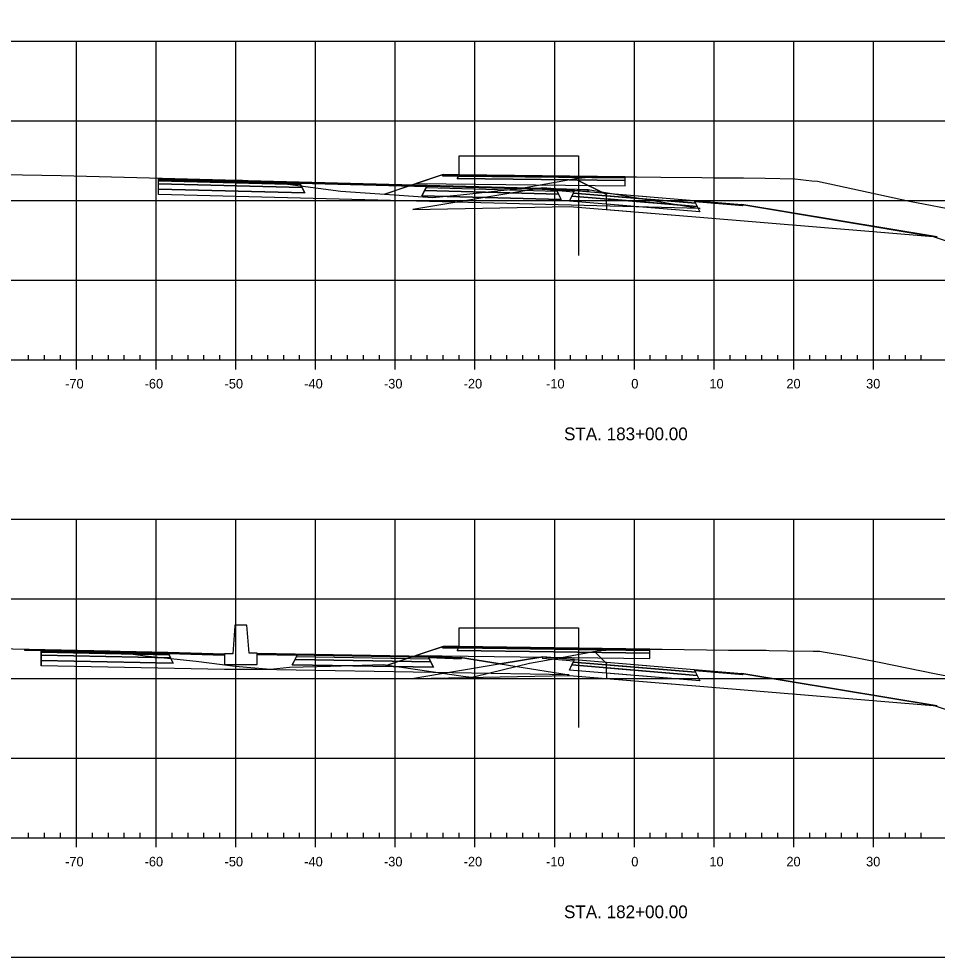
# Model space of a CAD drawing. Extents: x 659657 to 668193, y 633084 to 648639.
# Drawn here: x 667235.3 to 667350.5, y 643502.4 to 643620.2 of the extents above; entities that cross this region are included whole.
import ezdxf

# ---------------------------------------------------------------- set-up
doc = ezdxf.new("R2010")
doc.units = 0
for name, color, linetype in [('Default', 7, 'Continuous'), ('R_Axis', 7, 'Continuous'), ('R_Axis Annot', 7, 'Continuous'), ('R_Exist Surface', 7, 'Continuous'), ('R_Fin Surface', 7, 'Continuous'), ('R_Grid', 7, 'Continuous'), ('R_MOT_Stage 1B', 7, 'Continuous'), ('R_Sub Surface', 7, 'Continuous'), ('T_SIGNAL CONTROL CABINET', 7, 'Continuous'), ('TEMP_SIGNAL_HEAD_STAGE 5', 7, 'Continuous'), ('TEMP_SIGNAL_HEAD_STAGE4', 7, 'Continuous')]:
    doc.layers.add(name, color=color, linetype=linetype)

msp = doc.modelspace()

# ---------------------------------------------------------------- linework, layer by layer
for points in [[(667311.35, 643600.38), (667290.51, 643600.63), (667288.52, 643600.65), (667288.43, 643600.49), (667290.43, 643600.46), (667311.35, 643600.22)], [(667252.8, 643600.2), (667270.44, 643599.74), (667286.54, 643599.33), (667302.64, 643598.91), (667306.66, 643598.75), (667306.75, 643598.58), (667302.72, 643598.74), (667286.46, 643599.16), (667270.53, 643599.57), (667252.8, 643600.03)], [(667320.01, 643597.39), (667320.19, 643597.04), (667304.85, 643598.31), (667305.01, 643598.64)], [(667320.01, 643597.39), (667320.19, 643597.04), (667309.01, 643597.97), (667309.01, 643598.3)], [(667261.1, 643540.48), (667261.1, 643539.14), (667265.18, 643539.14), (667265.18, 643540.56), (667264.16, 643540.56), (667263.89, 643544.06), (667262.39, 643544.06), (667262.39, 643543.98), (667262.12, 643540.48)], [(667314.45, 643541.08), (667290.51, 643541.38), (667288.51, 643541.4), (667288.43, 643541.23), (667290.43, 643541.21), (667314.45, 643540.91)], [(667236.03, 643541.06), (667253.96, 643540.69), (667261.1, 643540.48), (667261.1, 643540.31), (667254.04, 643540.52), (667236.03, 643540.89)], [(667265.18, 643540.56), (667286.61, 643540.18), (667290.69, 643540.03), (667290.78, 643539.86), (667286.69, 643540.01), (667265.18, 643540.4)], [(667320.01, 643538.51), (667320.19, 643538.16), (667304.85, 643539.44), (667305.01, 643539.76)], [(667320.01, 643538.51), (667320.19, 643538.16), (667309.01, 643539.09), (667309.01, 643539.43)]]:
    msp.add_lwpolyline(points, close=True)
at = {"layer": 'Default'}
for points in [[(667281.18, 643598.2), (667282.49, 643598.64), (667285.15, 643599.53), (667288.21, 643600.55), (667288.52, 643600.65), (667289.11, 643600.65), (667290.51, 643600.63), (667306.92, 643600.44), (667311.35, 643600.38)], [(667300.93, 643598.8), (667301.01, 643598.97), (667305.01, 643598.64), (667320.01, 643597.39), (667326.01, 643596.89), (667350.01, 643592.89), (667356.33, 643590.79), (667369.66, 643595.73), (667369.96, 643595.84), (667384.87, 643600.81), (667384.91, 643600.81), (667386.6, 643600.88)], [(667305.04, 643600.12), (667309.01, 643598.14), (667309.01, 643598.3), (667320.01, 643597.39), (667326.01, 643596.89), (667350.01, 643592.89), (667356.33, 643590.79), (667359.49, 643594.1), (667359.56, 643594.18), (667360.58, 643595.23), (667371.01, 643598.68), (667374.76, 643599.21), (667375.02, 643599.25), (667386.6, 643600.88)], [(667281.52, 643539.07), (667282.82, 643539.5), (667285.14, 643540.28), (667286.33, 643540.67), (667288.51, 643541.4), (667289.23, 643541.39), (667290.51, 643541.38), (667299.39, 643541.27), (667314.45, 643541.08)], [(667290.69, 643540.03), (667295.66, 643539.2), (667301.01, 643540.09), (667305.01, 643539.76), (667320.01, 643538.51), (667326.01, 643538.02), (667350.01, 643534.02), (667358.19, 643531.29), (667388.17, 643541.28)], [(667307.49, 643540.78), (667309.01, 643539.26), (667309.01, 643539.43), (667320.01, 643538.51), (667326.01, 643538.02), (667350.01, 643534.02), (667358.19, 643531.29), (667388.17, 643541.28)]]:
    msp.add_lwpolyline(points, dxfattribs=at)
at = {"layer": 'R_Axis'}
for p, q in [((667236.51, 643577.39), (667236.51, 643577.99)), ((667238.51, 643577.39), (667238.51, 643577.99)), ((667240.51, 643577.39), (667240.51, 643577.99)), ((667242.51, 643576.19), (667242.51, 643578.59)), ((667244.51, 643577.39), (667244.51, 643577.99)), ((667246.51, 643577.39), (667246.51, 643577.99)), ((667248.51, 643577.39), (667248.51, 643577.99)), ((667250.51, 643577.39), (667250.51, 643577.99)), ((667252.51, 643576.19), (667252.51, 643578.59)), ((667254.51, 643577.39), (667254.51, 643577.99)), ((667256.51, 643577.39), (667256.51, 643577.99)), ((667258.51, 643577.39), (667258.51, 643577.99)), ((667260.51, 643577.39), (667260.51, 643577.99)), ((667262.51, 643576.19), (667262.51, 643578.59)), ((667264.51, 643577.39), (667264.51, 643577.99)), ((667266.51, 643577.39), (667266.51, 643577.99)), ((667268.51, 643577.39), (667268.51, 643577.99)), ((667270.51, 643577.39), (667270.51, 643577.99)), ((667272.51, 643576.19), (667272.51, 643578.59)), ((667274.51, 643577.39), (667274.51, 643577.99)), ((667276.51, 643577.39), (667276.51, 643577.99)), ((667278.51, 643577.39), (667278.51, 643577.99)), ((667280.51, 643577.39), (667280.51, 643577.99)), ((667282.51, 643576.19), (667282.51, 643578.59)), ((667284.51, 643577.39), (667284.51, 643577.99)), ((667286.51, 643577.39), (667286.51, 643577.99)), ((667288.51, 643577.39), (667288.51, 643577.99)), ((667290.51, 643577.39), (667290.51, 643577.99)), ((667292.51, 643576.19), (667292.51, 643578.59)), ((667294.51, 643577.39), (667294.51, 643577.99)), ((667296.51, 643577.39), (667296.51, 643577.99)), ((667298.51, 643577.39), (667298.51, 643577.99)), ((667300.51, 643577.39), (667300.51, 643577.99)), ((667302.51, 643576.19), (667302.51, 643578.59)), ((667304.51, 643577.39), (667304.51, 643577.99)), ((667306.51, 643577.39), (667306.51, 643577.99)), ((667308.51, 643577.39), (667308.51, 643577.99)), ((667310.51, 643577.39), (667310.51, 643577.99)), ((667312.51, 643576.19), (667312.51, 643578.59)), ((667314.51, 643577.39), (667314.51, 643577.99)), ((667316.51, 643577.39), (667316.51, 643577.99)), ((667318.51, 643577.39), (667318.51, 643577.99)), ((667320.51, 643577.39), (667320.51, 643577.99)), ((667322.51, 643576.19), (667322.51, 643578.59)), ((667324.51, 643577.39), (667324.51, 643577.99)), ((667326.51, 643577.39), (667326.51, 643577.99)), ((667328.51, 643577.39), (667328.51, 643577.99)), ((667330.51, 643577.39), (667330.51, 643577.99)), ((667332.51, 643576.19), (667332.51, 643578.59)), ((667334.51, 643577.39), (667334.51, 643577.99)), ((667336.51, 643577.39), (667336.51, 643577.99)), ((667338.51, 643577.39), (667338.51, 643577.99)), ((667340.51, 643577.39), (667340.51, 643577.99)), ((667342.51, 643576.19), (667342.51, 643578.59)), ((667344.51, 643577.39), (667344.51, 643577.99)), ((667346.51, 643577.39), (667346.51, 643577.99)), ((667348.51, 643577.39), (667348.51, 643577.99)), ((667162.51, 643577.39), (667462.51, 643577.39)), ((667236.51, 643517.39), (667236.51, 643517.99)), ((667238.51, 643517.39), (667238.51, 643517.99)), ((667240.51, 643517.39), (667240.51, 643517.99)), ((667242.51, 643516.19), (667242.51, 643518.59)), ((667244.51, 643517.39), (667244.51, 643517.99)), ((667246.51, 643517.39), (667246.51, 643517.99)), ((667248.51, 643517.39), (667248.51, 643517.99)), ((667250.51, 643517.39), (667250.51, 643517.99)), ((667252.51, 643516.19), (667252.51, 643518.59)), ((667254.51, 643517.39), (667254.51, 643517.99)), ((667256.51, 643517.39), (667256.51, 643517.99)), ((667258.51, 643517.39), (667258.51, 643517.99)), ((667260.51, 643517.39), (667260.51, 643517.99)), ((667262.51, 643516.19), (667262.51, 643518.59)), ((667264.51, 643517.39), (667264.51, 643517.99)), ((667266.51, 643517.39), (667266.51, 643517.99)), ((667268.51, 643517.39), (667268.51, 643517.99)), ((667270.51, 643517.39), (667270.51, 643517.99)), ((667272.51, 643516.19), (667272.51, 643518.59)), ((667274.51, 643517.39), (667274.51, 643517.99)), ((667276.51, 643517.39), (667276.51, 643517.99)), ((667278.51, 643517.39), (667278.51, 643517.99)), ((667280.51, 643517.39), (667280.51, 643517.99)), ((667282.51, 643516.19), (667282.51, 643518.59)), ((667284.51, 643517.39), (667284.51, 643517.99)), ((667286.51, 643517.39), (667286.51, 643517.99)), ((667288.51, 643517.39), (667288.51, 643517.99)), ((667290.51, 643517.39), (667290.51, 643517.99)), ((667292.51, 643516.19), (667292.51, 643518.59)), ((667294.51, 643517.39), (667294.51, 643517.99)), ((667296.51, 643517.39), (667296.51, 643517.99)), ((667298.51, 643517.39), (667298.51, 643517.99)), ((667300.51, 643517.39), (667300.51, 643517.99)), ((667302.51, 643516.19), (667302.51, 643518.59)), ((667304.51, 643517.39), (667304.51, 643517.99)), ((667306.51, 643517.39), (667306.51, 643517.99)), ((667308.51, 643517.39), (667308.51, 643517.99)), ((667310.51, 643517.39), (667310.51, 643517.99)), ((667312.51, 643516.19), (667312.51, 643518.59)), ((667314.51, 643517.39), (667314.51, 643517.99)), ((667316.51, 643517.39), (667316.51, 643517.99)), ((667318.51, 643517.39), (667318.51, 643517.99)), ((667320.51, 643517.39), (667320.51, 643517.99)), ((667322.51, 643516.19), (667322.51, 643518.59)), ((667324.51, 643517.39), (667324.51, 643517.99)), ((667326.51, 643517.39), (667326.51, 643517.99)), ((667328.51, 643517.39), (667328.51, 643517.99)), ((667330.51, 643517.39), (667330.51, 643517.99)), ((667332.51, 643516.19), (667332.51, 643518.59)), ((667334.51, 643517.39), (667334.51, 643517.99)), ((667336.51, 643517.39), (667336.51, 643517.99)), ((667338.51, 643517.39), (667338.51, 643517.99)), ((667340.51, 643517.39), (667340.51, 643517.99)), ((667342.51, 643516.19), (667342.51, 643518.59)), ((667344.51, 643517.39), (667344.51, 643517.99)), ((667346.51, 643517.39), (667346.51, 643517.99)), ((667348.51, 643517.39), (667348.51, 643517.99)), ((667162.51, 643517.39), (667462.51, 643517.39))]:
    msp.add_line(p, q, dxfattribs=at)
at = {"layer": 'R_Exist Surface'}
for points in [[(667230.83, 643600.71), (667240.61, 643600.51), (667262.76, 643599.94), (667263.1, 643599.93), (667263.19, 643599.93), (667263.34, 643599.93), (667263.66, 643599.91), (667266.99, 643599.73), (667267.78, 643599.62), (667275.66, 643598.56), (667281.8, 643598.16), (667287.2, 643597.78), (667290.69, 643598.12), (667298.08, 643598.9), (667303.52, 643599.86), (667305.11, 643600.13), (667306.77, 643600.3), (667307.79, 643600.39), (667309.39, 643600.39), (667311.35, 643600.38), (667311.95, 643600.38), (667312.76, 643600.38), (667315.81, 643600.33), (667320.96, 643600.26), (667322.42, 643600.25), (667324.51, 643600.25), (667326.21, 643600.24), (667328.9, 643600.19), (667332.66, 643600.12), (667334.79, 643599.87), (667335.5, 643599.8), (667337.99, 643599.27), (667347.04, 643597.32), (667353.6, 643596.05)], [(667224.36, 643541.31), (667246.68, 643540.84), (667246.89, 643540.82), (667251.11, 643540.22), (667257.52, 643539.55), (667262.41, 643538.94), (667266.84, 643538.57), (667269.24, 643538.8), (667274.38, 643538.94), (667280.98, 643539.15), (667291.03, 643537.66), (667292.07, 643537.54), (667292.66, 643537.68), (667299.36, 643539.29), (667303.37, 643540.02), (667307.82, 643540.84), (667308.29, 643540.88), (667310.87, 643541.05), (667314.07, 643541.08), (667314.45, 643541.08), (667315.82, 643541.07), (667315.98, 643541.07), (667324.32, 643540.94), (667325.18, 643540.93), (667329.06, 643540.92), (667329.44, 643540.91), (667331.73, 643540.87), (667334.96, 643540.82), (667335.77, 643540.8), (667336.18, 643540.74), (667338.97, 643540.28), (667343.22, 643539.42), (667350.36, 643537.95), (667353.72, 643537.33)]]:
    msp.add_lwpolyline(points, dxfattribs=at)
at = {"layer": 'R_Fin Surface'}
for points in [[(667311.35, 643600.22), (667290.43, 643600.46), (667290.26, 643600.13), (667311.35, 643599.88)], [(667252.8, 643600.03), (667270.53, 643599.57), (667270.61, 643599.4), (667252.8, 643599.87)], [(667252.8, 643599.87), (667270.61, 643599.4), (667270.81, 643599.02), (667252.8, 643599.49)], [(667252.8, 643599.49), (667270.81, 643599.02), (667271.15, 643598.35), (667252.8, 643598.83)], [(667302.72, 643598.74), (667286.46, 643599.16), (667286.37, 643599), (667302.81, 643598.57)], [(667286.19, 643598.63), (667303, 643598.19), (667303.34, 643597.52), (667285.86, 643597.97)], [(667286.37, 643599), (667302.81, 643598.57), (667303, 643598.19), (667286.19, 643598.63)], [(667304.85, 643598.31), (667320.19, 643597.04), (667320.38, 643596.65), (667304.67, 643597.95)], [(667309.01, 643597.97), (667320.19, 643597.04), (667320.38, 643596.65), (667309, 643597.59)], [(667254.04, 643540.52), (667254.12, 643540.35), (667238.07, 643540.68), (667238.07, 643540.85)], [(667238.07, 643540.68), (667254.12, 643540.35), (667254.32, 643539.98), (667238.07, 643540.3)], [(667238.07, 643540.3), (667254.32, 643539.98), (667254.66, 643539.3), (667238.07, 643539.63)], [(667286.69, 643540.01), (667270.2, 643540.3), (667270.12, 643540.14), (667286.78, 643539.84)], [(667314.45, 643540.91), (667290.43, 643541.21), (667290.26, 643540.88), (667314.45, 643540.58)], [(667269.93, 643539.77), (667286.97, 643539.46), (667287.32, 643538.79), (667269.59, 643539.1)], [(667270.12, 643540.14), (667286.78, 643539.84), (667286.97, 643539.46), (667269.93, 643539.77)], [(667304.85, 643539.44), (667320.19, 643538.16), (667320.38, 643537.77), (667304.67, 643539.08)], [(667309.01, 643539.09), (667320.19, 643538.16), (667320.38, 643537.77), (667309, 643538.72)]]:
    msp.add_lwpolyline(points, close=True, dxfattribs=at)
at = {"layer": 'R_Grid'}
for p, q in [((667162.51, 643617.39), (667462.51, 643617.39)), ((667242.51, 643577.39), (667242.51, 643617.39)), ((667252.51, 643577.39), (667252.51, 643617.39)), ((667262.51, 643577.39), (667262.51, 643617.39)), ((667272.51, 643577.39), (667272.51, 643617.39)), ((667282.51, 643577.39), (667282.51, 643617.39)), ((667292.51, 643577.39), (667292.51, 643617.39)), ((667302.51, 643577.39), (667302.51, 643617.39)), ((667312.51, 643577.39), (667312.51, 643617.39)), ((667322.51, 643577.39), (667322.51, 643617.39)), ((667332.51, 643577.39), (667332.51, 643617.39)), ((667342.51, 643577.39), (667342.51, 643617.39)), ((667162.51, 643607.39), (667462.51, 643607.39)), ((667162.51, 643597.39), (667462.51, 643597.39)), ((667162.51, 643587.39), (667462.51, 643587.39)), ((667162.51, 643577.39), (667462.51, 643577.39)), ((667162.51, 643557.39), (667462.51, 643557.39)), ((667242.51, 643517.39), (667242.51, 643557.39)), ((667252.51, 643517.39), (667252.51, 643557.39)), ((667262.51, 643517.39), (667262.51, 643557.39)), ((667272.51, 643517.39), (667272.51, 643557.39)), ((667282.51, 643517.39), (667282.51, 643557.39)), ((667292.51, 643517.39), (667292.51, 643557.39)), ((667302.51, 643517.39), (667302.51, 643557.39)), ((667312.51, 643517.39), (667312.51, 643557.39)), ((667322.51, 643517.39), (667322.51, 643557.39)), ((667332.51, 643517.39), (667332.51, 643557.39)), ((667342.51, 643517.39), (667342.51, 643557.39)), ((667162.51, 643547.39), (667462.51, 643547.39)), ((667162.51, 643537.39), (667462.51, 643537.39)), ((667162.51, 643527.39), (667462.51, 643527.39)), ((667162.51, 643517.39), (667462.51, 643517.39))]:
    msp.add_line(p, q, dxfattribs=at)
at = {"layer": 'R_MOT_Stage 1B'}
for points in [[(667290.51, 643600.63), (667290.51, 643602.99), (667305.51, 643602.99), (667305.51, 643590.5)], [(667290.51, 643541.38), (667290.51, 643543.73), (667305.51, 643543.73), (667305.51, 643531.24)]]:
    msp.add_lwpolyline(points, dxfattribs=at)
at = {"layer": 'R_Sub Surface'}
for points in [[(667311.35, 643599.88), (667290.26, 643600.13), (667290.43, 643600.46), (667311.35, 643600.22), (667290.43, 643600.46), (667288.43, 643600.49), (667288.52, 643600.65), (667285.15, 643599.53), (667311.35, 643599.22)], [(667252.8, 643598.83), (667271.15, 643598.35), (667270.53, 643599.57), (667286.46, 643599.16), (667285.86, 643597.97), (667303.34, 643597.52), (667302.72, 643598.74), (667306.75, 643598.58), (667306.66, 643598.75), (667320.75, 643596.4), (667252.8, 643598.16)], [(667304.67, 643597.95), (667320.38, 643596.65), (667320.73, 643595.95), (667304.35, 643597.31)], [(667309, 643597.59), (667320.38, 643596.65), (667320.73, 643595.95), (667309, 643596.93)], [(667314.45, 643540.58), (667290.26, 643540.88), (667290.43, 643541.21), (667314.45, 643540.91), (667290.43, 643541.21), (667288.43, 643541.23), (667288.51, 643541.4), (667285.14, 643540.28), (667314.45, 643539.91)], [(667238.07, 643539.63), (667254.66, 643539.3), (667254.04, 643540.52), (667261.1, 643540.31), (667261.1, 643539.14), (667265.18, 643539.14), (667265.18, 643540.4), (667270.2, 643540.3), (667269.59, 643539.1), (667287.32, 643538.79), (667286.69, 643540.01), (667290.78, 643539.86), (667290.69, 643540.03), (667304.32, 643537.84), (667265.18, 643538.52), (667261.1, 643538.52), (667238.07, 643538.97)], [(667304.67, 643539.08), (667320.38, 643537.77), (667320.73, 643537.07), (667304.35, 643538.43)], [(667309, 643538.72), (667320.38, 643537.77), (667320.73, 643537.07), (667309, 643538.05)]]:
    msp.add_lwpolyline(points, close=True, dxfattribs=at)
for points in [[(667301.01, 643598.97), (667284.7, 643596.25), (667304.35, 643596.64), (667320.73, 643595.28), (667350.5, 643592.81), (667326.01, 643596.89)], [(667309, 643596.93), (667308.99, 643596.26), (667320.73, 643595.28), (667350.5, 643592.81), (667326.01, 643596.89)], [(667301.01, 643540.09), (667284.82, 643537.39), (667304.35, 643537.76), (667320.73, 643536.4), (667350.5, 643533.93), (667326.01, 643538.02)], [(667309, 643538.05), (667308.99, 643537.38), (667320.73, 643536.4), (667350.5, 643533.93), (667326.01, 643538.02)]]:
    msp.add_lwpolyline(points, dxfattribs=at)
at = {"layer": 'T_SIGNAL CONTROL CABINET'}
msp.add_lwpolyline([(667152.51, 643502.39), (667492.51, 643502.39), (667492.51, 643722.39), (667152.51, 643722.39)], close=True, dxfattribs=at)
at = {"layer": 'TEMP_SIGNAL_HEAD_STAGE 5'}
for points in [[(667288.52, 643600.65), (667281.18, 643598.2)], [(667326.01, 643596.89), (667350.01, 643592.89), (667356.33, 643590.79), (667386.6, 643600.88)], [(667326.01, 643596.89), (667350.01, 643592.89), (667356.33, 643590.79), (667386.6, 643600.88)], [(667309.01, 643598.3), (667309.01, 643598.14), (667305.04, 643600.12)], [(667288.51, 643541.4), (667281.52, 643539.07)], [(667238.07, 643540.85), (667238.07, 643538.97)], [(667309.01, 643539.43), (667309.01, 643539.26), (667307.49, 643540.78)], [(667326.01, 643538.02), (667350.01, 643534.02), (667358.19, 643531.29), (667388.17, 643541.28)], [(667326.01, 643538.02), (667350.01, 643534.02), (667358.19, 643531.29), (667388.17, 643541.28)], [(667301.01, 643540.09), (667295.66, 643539.2), (667290.69, 643540.03)]]:
    msp.add_lwpolyline(points, dxfattribs=at)
at = {"layer": 'TEMP_SIGNAL_HEAD_STAGE4'}
for points in [[(667305.01, 643598.64), (667301.01, 643598.97), (667301.01, 643598.97), (667300.93, 643598.8), (667301.01, 643598.8), (667304.93, 643598.47)], [(667320.01, 643597.39), (667326.01, 643596.89), (667326.1, 643596.73), (667320.1, 643597.22)], [(667320.01, 643597.39), (667326.01, 643596.89), (667326.1, 643596.73), (667320.1, 643597.22)], [(667305.01, 643539.76), (667301.01, 643540.09), (667301.01, 643540.09), (667300.93, 643539.92), (667301.01, 643539.92), (667304.93, 643539.59)], [(667320.01, 643538.51), (667326.01, 643538.02), (667326.1, 643537.85), (667320.1, 643538.35)], [(667320.01, 643538.51), (667326.01, 643538.02), (667326.1, 643537.85), (667320.1, 643538.35)]]:
    msp.add_lwpolyline(points, close=True, dxfattribs=at)

# ---------------------------------------------------------------- texts
at = {"layer": 'R_Axis Annot'}
for s, height, p in [('-70', 1.2, (667241.09, 643573.79)), ('-60', 1.2, (667251.06, 643573.79)), ('-50', 1.2, (667261.09, 643573.79)), ('-40', 1.2, (667271.09, 643573.79)), ('-30', 1.2, (667281.09, 643573.79)), ('-20', 1.2, (667291.09, 643573.79)), ('-10', 1.2, (667301.43, 643573.79)), ('0', 1.2, (667312.12, 643573.79)), ('10', 1.2, (667321.92, 643573.79)), ('20', 1.2, (667331.58, 643573.79)), ('30', 1.2, (667341.58, 643573.79)), ('STA. 183+00.00', 1.6, (667303.68, 643567.29)), ('-70', 1.2, (667241.09, 643513.79)), ('-60', 1.2, (667251.06, 643513.79)), ('-50', 1.2, (667261.09, 643513.79)), ('-40', 1.2, (667271.09, 643513.79)), ('-30', 1.2, (667281.09, 643513.79)), ('-20', 1.2, (667291.09, 643513.79)), ('-10', 1.2, (667301.43, 643513.79)), ('0', 1.2, (667312.12, 643513.79)), ('10', 1.2, (667321.92, 643513.79)), ('20', 1.2, (667331.58, 643513.79)), ('30', 1.2, (667341.58, 643513.79)), ('STA. 182+00.00', 1.6, (667303.68, 643507.29))]:
    msp.add_text(s, height=height, dxfattribs=at).set_placement(p)

doc.saveas('drawing.dxf')
